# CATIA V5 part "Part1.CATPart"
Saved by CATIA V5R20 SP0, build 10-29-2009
Part number: Part1
Bounding box of the stored display mesh (mm): x -100 to 100, y -100 to 100, z 0 to 300
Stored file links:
  C:\Users\Orange\Desktop\Assembly Design-5\Part1.CATPart
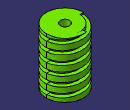
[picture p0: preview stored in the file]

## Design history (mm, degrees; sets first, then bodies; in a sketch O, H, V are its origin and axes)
Body1 (main body)
  Sketch1 on xy-plane, origin (0, 0, 0), H (1, 0, 0), V (0, 1, 0)
    circle A1 centre (0, 0) radius 100
    point P1 (0, 100)
    coincidence: A1 P1, P1 V
  Pad1: profile Sketch1, direction (0, 0, 1), length 300
  Sketch2 on zx-plane, origin (0, 0, 0), H (-1, 0, 0), V (0, 0, 1)
    point P1 (100, 300)
  Helix1: Direction Sketch2.V, RefPoint Sketch2, Pitch 50, Height 300, TaperAngle 0
  Plane1: type Normal, Curve Helix1, RefPoint Sketch2
  Sketch3 on Plane1, origin (0, -23.723, 1.8878), H (-1, 0, 0), V (0, 0.0793, 0.9968)
    line L1 (100, 310) -> (80, 310)
    line L2 (80, 310) -> (80, 290)
    line L3 (80, 290) -> (100, 290)
    line L4 (100, 290) -> (100, 310)
    horizontal: L1 H, L3 H
    vertical: L2 V, L4 V
  Slot1: profile Sketch3, centre curve Helix1
  Sketch4 on end face of Pad1, origin (0, 0, 300), H (1, 0, 0), V (0, 1, 0)
    point P1 (0, 0)
  Hole1: placed by Sketch4, at (0, 0, 300) direction (0, 0, -1), diameter 50, through (limit type 3)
